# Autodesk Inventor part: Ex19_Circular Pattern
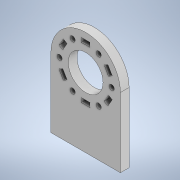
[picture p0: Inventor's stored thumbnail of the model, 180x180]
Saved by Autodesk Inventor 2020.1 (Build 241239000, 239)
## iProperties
Created: 2019-11
Part Number: Ex19_Circular Pattern
Material: Generic
Document SubType Name: Modeling
Designer: Synergysoft Dell02
Density: 1 g/cm^3
Appearance: Default
Author: Synergysoft Dell02
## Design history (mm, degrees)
sketch "Sketch1"
  geometry: L1 (0, 0)-(0, 80); L2 (80, 80)-(80, 0); L3 (80, 0)-(0, 0); C1 r 20 at (40, 80); A1 r 40 centre (40, 80) between (80, 80) and (0, 80)
  constraints: 6 end point, 2 centre point, 2 point on circle, 1 coincident, 1 horizontal alignment, 1 parallel, 1 perpendicular, 1 tangent, 1 vertical
  dimensions: "d0" = 80 distance of L1.start L1.end; "d2" = 80 distance of L2.end L1.start; "d3" = 40 diameter of C1
extrude "Extrusion1" new body sketch "Sketch1" distance "d4" = 10; taper "d5" = 0 deg
sketch "Sketch2" dims "d6" = 60
  geometry: L1 (35, 112.5)-(45, 112.5); L2 (45, 112.5)-(45, 107.5); L3 (45, 107.5)-(35, 107.5); L4 (35, 107.5)-(35, 112.5); L5 (35, 112.5)-(45, 107.5); L6 (45, 112.5)-(35, 107.5); C1 r 20 at (40, 80) reference; 4 further points
  constraints: 12 end point, 3 midpoint, 2 parallel, 2 vertical alignment, 1 horizontal, 1 perpendicular, 3 other
  dimensions: "d7" = 10 distance of L2.end L3.end; "d8" = 5 distance of L1.end L2.end
extrude "Extrusion2" cut sketch "Sketch2" extent not by distance; stored distance "d9" = 0; taper "d10" = 0 deg
pattern_circular "Circular Pattern1" dims angle "d12" = 360 deg
sketch "Sketch3" dims "d14" = 60
  geometry: C1 r 20 at (40, 80) reference; C2 r 3 at (70, 80); 2 further points
  constraints: 2 horizontal alignment, 1 centre point, 3 other
  dimensions: "d15" = 6 diameter of C2
extrude "Extrusion3" cut sketch "Sketch3" extent not by distance; stored distance "d16" = 0; taper "d17" = 0 deg
pattern_circular "Circular Pattern2" dims angle "d19" = 360 deg
body "Solid1"
